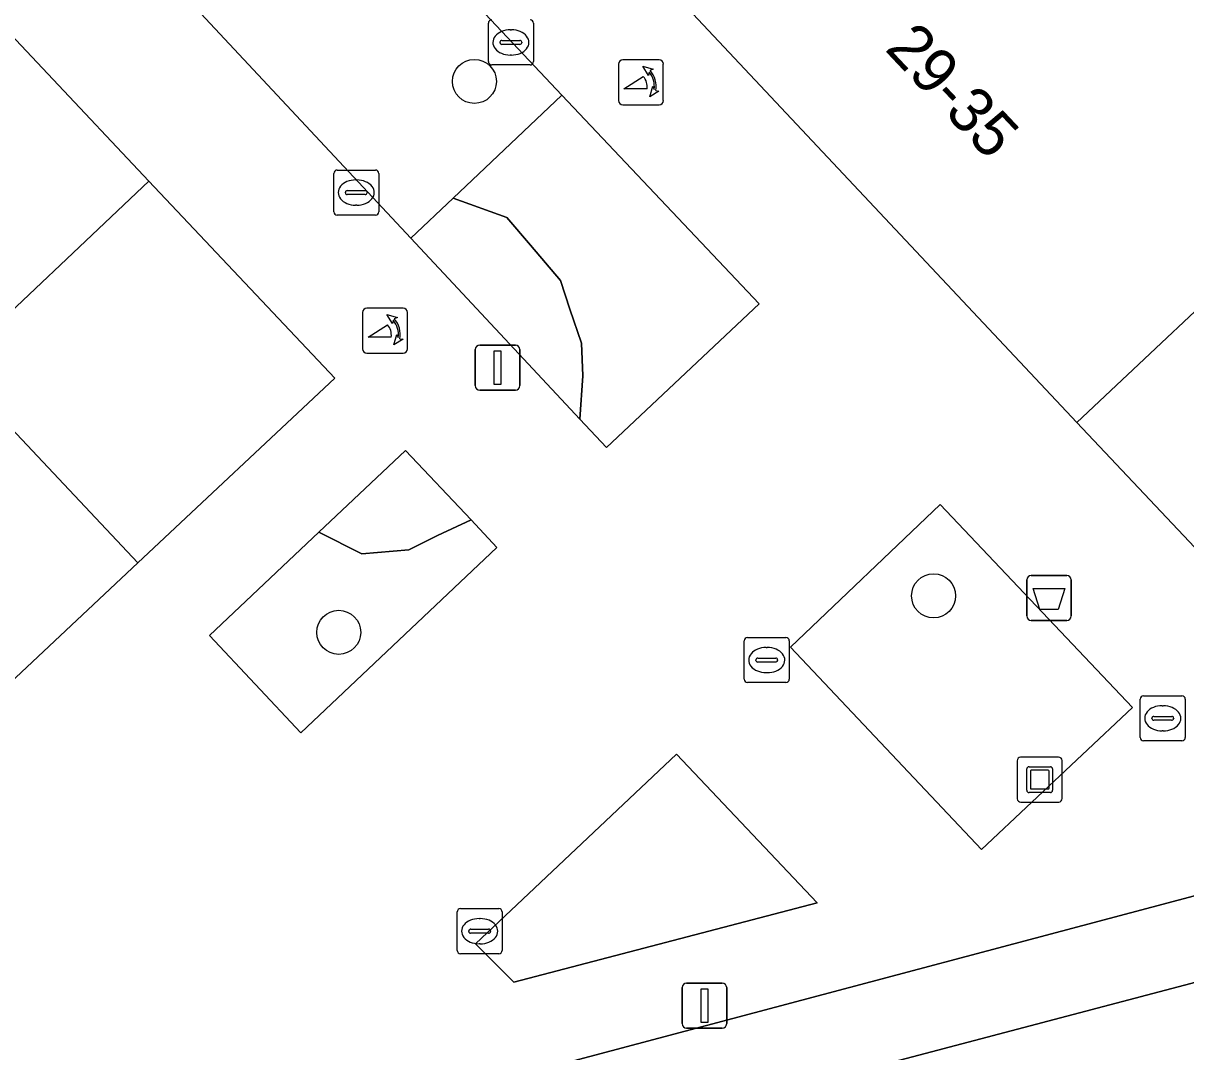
# Model space of a CAD drawing. Extents: x 162542 to 163147, y 380779 to 381521.
# Drawn here: x 162936.38 to 162962.19, y 381184.48 to 381207.32 of the extents above; entities that cross this region are included whole.
import ezdxf

# ---------------------------------------------------------------- set-up
doc = ezdxf.new("R2010")
doc.units = 0
for name, color, linetype in [('IMGEO_Afvalbak', 7, 'Continuous'), ('IMGEO_Boom', 7, 'Continuous'), ('IMGEO_Erf', 7, 'Continuous'), ('IMGEO_Groenvoorziening', 7, 'Continuous'), ('IMGEO_Hek', 7, 'Continuous'), ('IMGEO_Kolk', 7, 'Continuous'), ('IMGEO_Kunstobject', 7, 'Continuous'), ('IMGEO_Lichtmast', 7, 'Continuous'), ('IMGEO_Muur', 7, 'Continuous'), ('IMGEO_Pand', 7, 'Continuous'), ('IMGEO_Pand_nummerreeks', 7, 'Continuous'), ('IMGEO_Parkeervlak_open', 7, 'Continuous'), ('IMGEO_Poller', 7, 'Continuous'), ('IMGEO_Rijbaan_lokaal_open', 7, 'Continuous'), ('IMGEO_Rioolput', 7, 'Continuous'), ('IMGEO_Voetpad_open', 7, 'Continuous')]:
    doc.layers.add(name, color=color, linetype=linetype)

msp = doc.modelspace()

# ---------------------------------------------------------------- linework, layer by layer
at = {"layer": 'IMGEO_Afvalbak'}
for p, q in [((162958.662, 381194.16), (162958.662, 381194.96)), ((162958.662, 381194.96), (162958.662, 381194.16)), ((162958.762, 381195.06), (162959.552, 381195.06)), ((162959.552, 381195.06), (162958.762, 381195.06)), ((162959.652, 381194.96), (162959.652, 381194.16)), ((162959.652, 381194.16), (162959.652, 381194.96)), ((162959.552, 381194.06), (162958.762, 381194.06)), ((162958.762, 381194.06), (162959.552, 381194.06))]:
    msp.add_line(p, q, dxfattribs=at)
msp.add_lwpolyline([(162958.805, 381194.774), (162959.509, 381194.774), (162959.36, 381194.304), (162958.954, 381194.304), (162958.805, 381194.774)], dxfattribs=at)
for centre, start, end in [((162958.762, 381194.96), 90, 180), ((162958.762, 381194.96), 90, 180), ((162959.552, 381194.96), 0, 90), ((162959.552, 381194.96), 360, 90), ((162958.762, 381194.16), 180, 270), ((162958.762, 381194.16), 180, 270), ((162959.552, 381194.16), 270, 0), ((162959.552, 381194.16), 270, 0)]:
    msp.add_arc(centre, 0.1, start, end, dxfattribs=at)
at = {"layer": 'IMGEO_Boom'}
for centre in [(162946.396, 381206.032), (162956.594, 381194.609), (162943.384, 381193.797)]:
    msp.add_circle(centre, 0.489, dxfattribs=at)
at = {"layer": 'IMGEO_Erf'}
for points in [[(162939.164, 381203.82), (162934.812, 381199.7), (162938.919, 381195.337), (162943.3, 381199.444)], [(162968.257, 381198.213), (162964.15, 381202.572), (162959.774, 381198.46), (162963.89, 381194.094)]]:
    msp.add_lwpolyline(points, close=True, dxfattribs=at)
at = {"layer": 'IMGEO_Groenvoorziening'}
for points in [[(162948.336, 381205.724), (162945.924, 381203.441), (162947.117, 381203.009), (162947.641, 381202.398), (162948.309, 381201.613), (162948.513, 381200.974), (162948.774, 381200.218), (162948.803, 381199.491), (162948.741, 381198.532), (162949.331, 381197.901), (162952.72, 381201.096)], [(162945.924, 381203.441), (162944.983, 381202.551), (162948.741, 381198.532), (162948.803, 381199.491), (162948.774, 381200.218), (162948.513, 381200.974), (162948.309, 381201.613), (162947.641, 381202.398), (162947.117, 381203.009)], [(162944.864, 381197.833), (162942.941, 381196.018), (162943.894, 381195.542), (162944.939, 381195.632), (162945.575, 381195.95), (162946.321, 381196.293)], [(162961.012, 381192.127), (162956.739, 381196.635), (162953.416, 381193.464), (162957.656, 381188.976)], [(162946.898, 381195.683), (162946.321, 381196.293), (162945.575, 381195.95), (162944.939, 381195.632), (162943.894, 381195.542), (162942.941, 381196.018), (162940.51, 381193.725), (162942.545, 381191.565)], [(162950.882, 381191.089), (162946.421, 381186.882), (162947.274, 381186.026), (162954.012, 381187.786)]]:
    msp.add_lwpolyline(points, close=True, dxfattribs=at)
at = {"layer": 'IMGEO_Hek'}
for points in [[(162943.3, 381199.444), (162939.164, 381203.82)], [(162938.919, 381195.337), (162943.3, 381199.444)]]:
    msp.add_lwpolyline(points, dxfattribs=at)
at = {"layer": 'IMGEO_Kolk'}
for p, q in [((162946.706, 381206.472), (162946.706, 381207.324)), ((162947.707, 381207.324), (162947.707, 381206.472)), ((162947.194, 381207.178), (162947.219, 381207.178)), ((162946.965, 381206.892), (162946.965, 381206.904)), ((162947.403, 381206.855), (162947.005, 381206.855)), ((162947.008, 381206.941), (162947.406, 381206.941)), ((162947.449, 381206.904), (162947.449, 381206.892)), ((162947.217, 381206.618), (162947.192, 381206.618)), ((162947.633, 381206.398), (162946.781, 381206.398)), ((162943.272, 381203.138), (162943.272, 381203.99)), ((162943.347, 381204.064), (162944.199, 381204.064)), ((162944.273, 381203.99), (162944.273, 381203.138)), ((162943.76, 381203.844), (162943.785, 381203.844)), ((162943.531, 381203.558), (162943.531, 381203.57)), ((162943.969, 381203.521), (162943.571, 381203.521)), ((162943.574, 381203.607), (162943.972, 381203.607)), ((162944.015, 381203.57), (162944.015, 381203.558)), ((162943.783, 381203.284), (162943.758, 381203.284)), ((162944.199, 381203.064), (162943.347, 381203.064)), ((162952.388, 381192.755), (162952.388, 381193.607)), ((162952.463, 381193.681), (162953.315, 381193.681)), ((162953.389, 381193.607), (162953.389, 381192.755)), ((162952.876, 381193.461), (162952.901, 381193.461)), ((162952.647, 381193.175), (162952.647, 381193.187)), ((162953.085, 381193.138), (162952.687, 381193.138)), ((162952.69, 381193.224), (162953.088, 381193.224)), ((162953.131, 381193.187), (162953.131, 381193.175)), ((162952.899, 381192.901), (162952.874, 381192.901)), ((162953.315, 381192.681), (162952.463, 381192.681)), ((162946.088, 381187.66), (162946.94, 381187.66)), ((162946.013, 381186.734), (162946.013, 381187.586)), ((162946.501, 381187.44), (162946.526, 381187.44)), ((162947.014, 381187.586), (162947.014, 381186.734)), ((162946.272, 381187.154), (162946.272, 381187.166)), ((162946.315, 381187.203), (162946.713, 381187.203)), ((162946.756, 381187.166), (162946.756, 381187.154)), ((162946.71, 381187.117), (162946.312, 381187.117)), ((162946.524, 381186.88), (162946.499, 381186.88)), ((162946.94, 381186.66), (162946.088, 381186.66))]:
    msp.add_line(p, q, dxfattribs=at)
for points in [[(162946.706, 381206.472), (162946.706, 381207.324)], [(162947.707, 381207.324), (162947.707, 381206.472)], [(162947.633, 381206.398), (162946.781, 381206.398)], [(162943.272, 381203.138), (162943.272, 381203.99)], [(162943.347, 381204.064), (162944.199, 381204.064)], [(162944.273, 381203.99), (162944.273, 381203.138)], [(162944.199, 381203.064), (162943.347, 381203.064)], [(162952.388, 381192.755), (162952.388, 381193.607)], [(162952.463, 381193.681), (162953.315, 381193.681)], [(162953.389, 381193.607), (162953.389, 381192.755)], [(162953.315, 381192.681), (162952.463, 381192.681)], [(162946.088, 381187.66), (162946.94, 381187.66)], [(162946.013, 381186.734), (162946.013, 381187.586)], [(162947.014, 381187.586), (162947.014, 381186.734)], [(162946.94, 381186.66), (162946.088, 381186.66)]]:
    msp.add_lwpolyline(points, dxfattribs=at)
for centre, radius, start, end in [((162946.783, 381207.322), 0.0765, 91.552, 178.448), ((162946.783, 381207.322), 0.0765, 91.552, 178.448), ((162947.631, 381207.322), 0.0765, 1.552, 88.448), ((162947.631, 381207.322), 0.0765, 1.552, 88.448), ((162947.005, 381206.901), 0.0403, 85.8775, 175.7526), ((162947.002, 381206.891), 0.0366, 178.938, 274.7102), ((162947.406, 381206.898), 0.043, 264.8664, 352.4533), ((162947.41, 381206.903), 0.0386, 1.7309, 96.639), ((162946.783, 381206.474), 0.0765, 181.552, 268.448), ((162946.783, 381206.474), 0.0765, 181.552, 268.448), ((162947.631, 381206.474), 0.0765, 271.552, 358.448), ((162947.631, 381206.474), 0.0765, 271.552, 358.448), ((162943.349, 381203.988), 0.0765, 91.552, 178.448), ((162943.349, 381203.988), 0.0765, 91.552, 178.448), ((162944.197, 381203.988), 0.0765, 1.552, 88.448), ((162944.197, 381203.988), 0.0765, 1.552, 88.448), ((162943.571, 381203.567), 0.0403, 85.8775, 175.7526), ((162943.568, 381203.557), 0.0366, 178.938, 274.7102), ((162943.972, 381203.564), 0.043, 264.8664, 352.4533), ((162943.976, 381203.569), 0.0386, 1.7309, 96.639), ((162943.349, 381203.14), 0.0765, 181.552, 268.448), ((162943.349, 381203.14), 0.0765, 181.552, 268.448), ((162944.197, 381203.14), 0.0765, 271.552, 358.448), ((162944.197, 381203.14), 0.0765, 271.552, 358.448), ((162952.465, 381193.605), 0.0765, 91.552, 178.448), ((162952.465, 381193.605), 0.0765, 91.552, 178.448), ((162953.313, 381193.605), 0.0765, 1.552, 88.448), ((162953.313, 381193.605), 0.0765, 1.552, 88.448), ((162952.687, 381193.184), 0.0403, 85.8775, 175.7526), ((162952.684, 381193.174), 0.0366, 178.938, 274.7102), ((162953.088, 381193.181), 0.043, 264.8664, 352.4533), ((162953.092, 381193.186), 0.0386, 1.7309, 96.639), ((162952.465, 381192.757), 0.0765, 181.552, 268.448), ((162952.465, 381192.757), 0.0765, 181.552, 268.448), ((162953.313, 381192.757), 0.0765, 271.552, 358.448), ((162953.313, 381192.757), 0.0765, 271.552, 358.448), ((162946.09, 381187.584), 0.0765, 91.552, 178.448), ((162946.09, 381187.584), 0.0765, 91.552, 178.448), ((162946.938, 381187.584), 0.0765, 1.552, 88.448), ((162946.938, 381187.584), 0.0765, 1.552, 88.448), ((162946.312, 381187.163), 0.0403, 85.8775, 175.7526), ((162946.309, 381187.153), 0.0366, 178.938, 274.7102), ((162946.713, 381187.16), 0.043, 264.8664, 352.4533), ((162946.717, 381187.165), 0.0386, 1.7309, 96.639), ((162946.09, 381186.736), 0.0765, 181.552, 268.448), ((162946.09, 381186.736), 0.0765, 181.552, 268.448), ((162946.938, 381186.736), 0.0765, 271.552, 358.448), ((162946.938, 381186.736), 0.0765, 271.552, 358.448)]:
    msp.add_arc(centre, radius, start, end, dxfattribs=at)
for centre, major_axis, ratio, start_param, end_param in [((162947.193, 381206.898), (-0.387, 0.002), 0.722429, 4.712389, 7.853982), ((162947.218, 381206.898), (-0.39, 0.002), 0.717154, 1.570796, 4.712389), ((162943.759, 381203.564), (-0.387, 0.002), 0.722429, 4.712389, 7.853982), ((162943.784, 381203.564), (-0.39, 0.002), 0.717154, 1.570796, 4.712389), ((162952.875, 381193.181), (-0.387, 0.002), 0.722429, 4.712389, 7.853982), ((162952.9, 381193.181), (-0.39, 0.002), 0.717154, 1.570796, 4.712389), ((162946.5, 381187.16), (-0.387, 0.002), 0.722429, 4.712389, 7.853982), ((162946.525, 381187.16), (-0.39, 0.002), 0.717154, 1.570796, 4.712389)]:
    msp.add_ellipse(centre, major_axis=major_axis, ratio=ratio, start_param=start_param, end_param=end_param, dxfattribs=at)
at = {"layer": 'IMGEO_Kunstobject'}
for p, q in [((162959.366, 381191.025), (162958.525, 381191.025)), ((162959.366, 381191.025), (162958.525, 381191.025)), ((162958.45, 381190.941), (162958.45, 381190.1)), ((162958.45, 381190.941), (162958.45, 381190.1)), ((162958.664, 381190.289), (162958.664, 381190.763)), ((162958.714, 381190.813), (162959.188, 381190.813)), ((162959.238, 381190.763), (162959.238, 381190.289)), ((162959.45, 381190.109), (162959.45, 381190.95)), ((162959.45, 381190.109), (162959.45, 381190.95)), ((162958.744, 381190.713), (162958.744, 381190.339)), ((162959.138, 381190.733), (162958.764, 381190.733)), ((162959.158, 381190.339), (162959.158, 381190.713)), ((162959.188, 381190.239), (162958.714, 381190.239)), ((162958.764, 381190.319), (162959.138, 381190.319)), ((162958.534, 381190.025), (162959.375, 381190.025)), ((162958.534, 381190.025), (162959.375, 381190.025))]:
    msp.add_line(p, q, dxfattribs=at)
for centre, radius, start, end in [((162958.528, 381190.947), 0.0779, 92.4484, 184.2845), ((162958.528, 381190.947), 0.0779, 92.4484, 184.2845), ((162959.372, 381190.947), 0.0779, 2.4484, 94.2845), ((162959.372, 381190.947), 0.0779, 2.4484, 94.2845), ((162958.714, 381190.763), 0.05, 90, 180), ((162959.188, 381190.763), 0.05, 360, 90), ((162958.764, 381190.713), 0.02, 90, 180), ((162959.138, 381190.713), 0.02, 360, 90), ((162958.714, 381190.289), 0.05, 180, 270), ((162958.764, 381190.339), 0.02, 180, 270), ((162959.138, 381190.339), 0.02, 270, 0), ((162959.188, 381190.289), 0.05, 270, 0), ((162958.528, 381190.103), 0.0779, 182.4484, 274.2845), ((162958.528, 381190.103), 0.0779, 182.4484, 274.2845), ((162959.372, 381190.103), 0.0779, 272.4484, 4.2845), ((162959.372, 381190.103), 0.0779, 272.4484, 4.2845)]:
    msp.add_arc(centre, radius, start, end, dxfattribs=at)
at = {"layer": 'IMGEO_Lichtmast'}
for p, q in [((162946.416, 381199.277), (162946.416, 381200.077)), ((162946.416, 381200.077), (162946.416, 381199.277)), ((162946.516, 381200.177), (162947.306, 381200.177)), ((162947.306, 381200.177), (162946.516, 381200.177)), ((162947.406, 381200.077), (162947.406, 381199.277)), ((162947.406, 381199.277), (162947.406, 381200.077)), ((162947.306, 381199.177), (162946.516, 381199.177)), ((162946.516, 381199.177), (162947.306, 381199.177)), ((162951.009, 381185.106), (162951.009, 381185.906)), ((162951.009, 381185.906), (162951.009, 381185.106)), ((162951.109, 381186.006), (162951.899, 381186.006)), ((162951.899, 381186.006), (162951.109, 381186.006)), ((162951.999, 381185.906), (162951.999, 381185.106)), ((162951.999, 381185.106), (162951.999, 381185.906)), ((162951.899, 381185.006), (162951.109, 381185.006)), ((162951.109, 381185.006), (162951.899, 381185.006))]:
    msp.add_line(p, q, dxfattribs=at)
for points in [[(162946.836, 381200.052), (162946.986, 381200.052), (162946.986, 381199.302), (162946.836, 381199.302), (162946.836, 381200.052)], [(162951.429, 381185.881), (162951.579, 381185.881), (162951.579, 381185.131), (162951.429, 381185.131), (162951.429, 381185.881)]]:
    msp.add_lwpolyline(points, dxfattribs=at)
for centre, start, end in [((162946.516, 381200.077), 90, 180), ((162946.516, 381200.077), 90, 180), ((162947.306, 381200.077), 0, 90), ((162947.306, 381200.077), 360, 90), ((162946.516, 381199.277), 180, 270), ((162946.516, 381199.277), 180, 270), ((162947.306, 381199.277), 270, 0), ((162947.306, 381199.277), 270, 0), ((162951.109, 381185.906), 90, 180), ((162951.109, 381185.906), 90, 180), ((162951.899, 381185.906), 0, 90), ((162951.899, 381185.906), 360, 90), ((162951.109, 381185.106), 180, 270), ((162951.109, 381185.106), 180, 270), ((162951.899, 381185.106), 270, 0), ((162951.899, 381185.106), 270, 0)]:
    msp.add_arc(centre, 0.1, start, end, dxfattribs=at)
at = {"layer": 'IMGEO_Muur'}
msp.add_lwpolyline([(162959.774, 381198.46), (162963.89, 381194.094)], dxfattribs=at)
at = {"layer": 'IMGEO_Pand'}
for points in [[(162956.596, 381220.8), (162956.867, 381220.513), (162951.756, 381215.746), (162951.824, 381215.673), (162955.597, 381211.645), (162951.248, 381207.533), (162959.774, 381198.46), (162964.15, 381202.572), (162968.257, 381198.213), (162981.688, 381210.831), (162964.931, 381228.644), (162962.674, 381226.519)], [(162939.164, 381203.82), (162934.676, 381208.594), (162930.637, 381212.889), (162926.266, 381208.779), (162922.498, 381212.786), (162922.327, 381212.968), (162917.212, 381208.149), (162917.043, 381208.328), (162913.41, 381204.905), (162910.674, 381202.328), (162908.709, 381200.476), (162910.511, 381198.541), (162910.938, 381198.083), (162912.597, 381196.303), (162913.121, 381195.741), (162917.122, 381191.446), (162921.624, 381186.774), (162925.455, 381182.694), (162930.161, 381187.114), (162938.919, 381195.337), (162934.812, 381199.7)]]:
    msp.add_lwpolyline(points, close=True, dxfattribs=at)
at = {"layer": 'IMGEO_Parkeervlak_open'}
msp.add_lwpolyline([(162945.307, 381183.409), (162944.204, 381183.118), (162943.854, 381183.025), (162937.074, 381181.191), (162920.542, 381176.676), (162920.963, 381174.947), (162923.178, 381175.528), (162939.834, 381180.075), (163029.671, 381203.749), (163029.17, 381205.595), (163009.881, 381200.547), (163008.469, 381200.178), (162968.263, 381189.504)], close=True, dxfattribs=at)
at = {"layer": 'IMGEO_Poller'}
for p, q in [((162950.498, 381206.509), (162949.69, 381206.509)), ((162950.498, 381206.509), (162949.69, 381206.509)), ((162949.596, 381206.414), (162949.596, 381205.607)), ((162949.596, 381206.414), (162949.596, 381205.607)), ((162950.592, 381205.607), (162950.592, 381206.414)), ((162950.592, 381205.607), (162950.592, 381206.414)), ((162949.69, 381205.512), (162950.498, 381205.512)), ((162949.69, 381205.512), (162950.498, 381205.512)), ((162943.913, 381200.902), (162943.913, 381200.095)), ((162943.913, 381200.902), (162943.913, 381200.095)), ((162944.815, 381200.997), (162944.007, 381200.997)), ((162944.815, 381200.997), (162944.007, 381200.997)), ((162944.909, 381200.095), (162944.909, 381200.902)), ((162944.909, 381200.095), (162944.909, 381200.902)), ((162944.007, 381200), (162944.815, 381200)), ((162944.007, 381200), (162944.815, 381200))]:
    msp.add_line(p, q, dxfattribs=at)
for points in [[(162950.275, 381206.238), (162950.263, 381206.165), (162950.138, 381206.37)], [(162950.138, 381206.37), (162950.369, 381206.304), (162950.298, 381206.272)], [(162950.231, 381205.865), (162949.718, 381205.865), (162950.148, 381206.14)], [(162950.291, 381205.693), (162950.357, 381205.924), (162950.387, 381205.856)], [(162950.423, 381205.829), (162950.495, 381205.818), (162950.291, 381205.693)], [(162944.592, 381200.726), (162944.58, 381200.653), (162944.455, 381200.858)], [(162944.455, 381200.858), (162944.686, 381200.792), (162944.615, 381200.76)], [(162944.548, 381200.353), (162944.035, 381200.353), (162944.465, 381200.628)], [(162944.608, 381200.181), (162944.674, 381200.412), (162944.704, 381200.344)], [(162944.74, 381200.317), (162944.812, 381200.306), (162944.608, 381200.181)]]:
    msp.add_lwpolyline(points, dxfattribs=at)
for centre, radius, start, end in [((162949.69, 381206.414), 0.0946, 90, 180), ((162949.69, 381206.414), 0.0946, 90, 180), ((162950.498, 381206.414), 0.0946, 0, 90), ((162950.498, 381206.414), 0.0946, 0, 90), ((162949.917, 381205.925), 0.476, 351.7527, 41.1691), ((162949.917, 381205.925), 0.516, 349.3569, 42.2912), ((162949.903, 381205.915), 0.332, 351.3247, 42.4854), ((162949.69, 381205.607), 0.0946, 180, 270), ((162949.69, 381205.607), 0.0946, 180, 270), ((162950.498, 381205.607), 0.0946, 270, 0), ((162950.498, 381205.607), 0.0946, 270, 0), ((162944.007, 381200.902), 0.0946, 90, 180), ((162944.007, 381200.902), 0.0946, 90, 180), ((162944.815, 381200.902), 0.0946, 0, 90), ((162944.815, 381200.902), 0.0946, 0, 90), ((162944.22, 381200.403), 0.332, 351.3247, 42.4854), ((162944.234, 381200.413), 0.476, 351.7527, 41.1691), ((162944.234, 381200.413), 0.516, 349.3569, 42.2912), ((162944.007, 381200.095), 0.0946, 180, 270), ((162944.007, 381200.095), 0.0946, 180, 270), ((162944.815, 381200.095), 0.0946, 270, 0), ((162944.815, 381200.095), 0.0946, 270, 0)]:
    msp.add_arc(centre, radius, start, end, dxfattribs=at)
at = {"layer": 'IMGEO_Rijbaan_lokaal_open'}
msp.add_lwpolyline([(163029.671, 381203.749), (162939.834, 381180.075), (162923.178, 381175.528), (162924.413, 381170.816), (162930.38, 381172.396), (162931.623, 381172.725), (162941.6, 381175.367), (162946.927, 381176.777), (162948.093, 381177.085), (162958.186, 381179.749), (162960.101, 381180.253), (162970.109, 381182.891), (162971.268, 381183.196), (162981.715, 381185.95), (162982.865, 381186.253), (162993.306, 381189.004), (162994.468, 381189.311), (163004.787, 381192.03)], dxfattribs=at)
at = {"layer": 'IMGEO_Rioolput'}
for p, q in [((162961.183, 381191.462), (162961.183, 381192.314)), ((162961.258, 381192.388), (162962.11, 381192.388)), ((162962.184, 381192.314), (162962.184, 381191.462)), ((162961.671, 381192.168), (162961.696, 381192.168)), ((162961.442, 381191.882), (162961.442, 381191.894)), ((162961.88, 381191.845), (162961.482, 381191.845)), ((162961.485, 381191.931), (162961.883, 381191.931)), ((162961.926, 381191.894), (162961.926, 381191.882)), ((162961.694, 381191.608), (162961.669, 381191.608)), ((162962.11, 381191.388), (162961.258, 381191.388))]:
    msp.add_line(p, q, dxfattribs=at)
for points in [[(162961.183, 381191.462), (162961.183, 381192.314)], [(162961.258, 381192.388), (162962.11, 381192.388)], [(162962.184, 381192.314), (162962.184, 381191.462)], [(162962.11, 381191.388), (162961.258, 381191.388)]]:
    msp.add_lwpolyline(points, dxfattribs=at)
for centre, radius, start, end in [((162961.26, 381192.312), 0.0765, 91.552, 178.448), ((162961.26, 381192.312), 0.0765, 91.552, 178.448), ((162962.108, 381192.312), 0.0765, 1.552, 88.448), ((162962.108, 381192.312), 0.0765, 1.552, 88.448), ((162961.482, 381191.891), 0.0403, 85.8775, 175.7526), ((162961.479, 381191.881), 0.0366, 178.938, 274.7102), ((162961.883, 381191.888), 0.043, 264.8664, 352.4533), ((162961.887, 381191.893), 0.0386, 1.7309, 96.639), ((162961.26, 381191.464), 0.0765, 181.552, 268.448), ((162961.26, 381191.464), 0.0765, 181.552, 268.448), ((162962.108, 381191.464), 0.0765, 271.552, 358.448), ((162962.108, 381191.464), 0.0765, 271.552, 358.448)]:
    msp.add_arc(centre, radius, start, end, dxfattribs=at)
for centre, major_axis, ratio, start_param, end_param in [((162961.67, 381191.888), (-0.387, 0.002), 0.722429, 4.712389, 7.853982), ((162961.695, 381191.888), (-0.39, 0.002), 0.717154, 1.570796, 4.712389)]:
    msp.add_ellipse(centre, major_axis=major_axis, ratio=ratio, start_param=start_param, end_param=end_param, dxfattribs=at)
at = {"layer": 'IMGEO_Voetpad_open'}
for points in [[(162865.48, 381282.064), (162871.275, 381275.979), (162871.311, 381275.941), (162873.07, 381274.077), (162878.582, 381268.238), (162880.297, 381266.406), (162887.54, 381258.657), (162894.031, 381251.782), (162897.699, 381247.866), (162926.773, 381216.999), (162930.637, 381212.889), (162934.676, 381208.594), (162939.164, 381203.82), (162943.3, 381199.444), (162938.919, 381195.337), (162930.161, 381187.114), (162925.455, 381182.694), (162921.793, 381179.222), (162849.909, 381160.144)], [(162850.91, 381158.201), (162882.303, 381166.521), (162903.648, 381172.331), (162920.542, 381176.676), (162937.074, 381181.191), (162936.958, 381181.61), (162944.091, 381183.522), (162944.204, 381183.118), (162945.307, 381183.409), (162968.263, 381189.504), (162966.757, 381191.138), (162965.477, 381192.532), (162963.89, 381194.094), (162959.774, 381198.46), (162951.248, 381207.533), (162947.383, 381211.626), (162906.029, 381255.574)], [(162902.789, 381254.064), (162910.507, 381245.873), (162912.542, 381243.713), (162914.411, 381241.729), (162918.482, 381237.409), (162927.981, 381227.327), (162928.987, 381226.26), (162932.052, 381223.007), (162948.336, 381205.724), (162952.72, 381201.096), (162949.331, 381197.901), (162948.741, 381198.532), (162944.983, 381202.551), (162928.747, 381219.915), (162928.487, 381220.193), (162925.489, 381223.396), (162924.695, 381224.244), (162915.191, 381234.33), (162911.139, 381238.659), (162908.622, 381241.317), (162907.224, 381242.793), (162899.498, 381250.953)]]:
    msp.add_lwpolyline(points, dxfattribs=at)
for points in [[(162932.052, 381223.007), (162931.343, 381222.344), (162928.747, 381219.915), (162944.983, 381202.551), (162945.924, 381203.441), (162948.336, 381205.724)], [(162942.941, 381196.018), (162944.864, 381197.833), (162946.321, 381196.293), (162946.898, 381195.683), (162942.545, 381191.565), (162940.51, 381193.725)], [(162956.739, 381196.635), (162961.012, 381192.127), (162957.656, 381188.976), (162953.416, 381193.464)], [(162946.421, 381186.882), (162950.882, 381191.089), (162954.012, 381187.786), (162947.274, 381186.026)]]:
    msp.add_lwpolyline(points, close=True, dxfattribs=at)

# ---------------------------------------------------------------- texts
at = {"layer": 'IMGEO_Pand_nummerreeks'}
msp.add_text('29-35', height=1, rotation=313.2568, dxfattribs=at).set_placement((162955.491, 381206.74))

doc.saveas('drawing.dxf')
